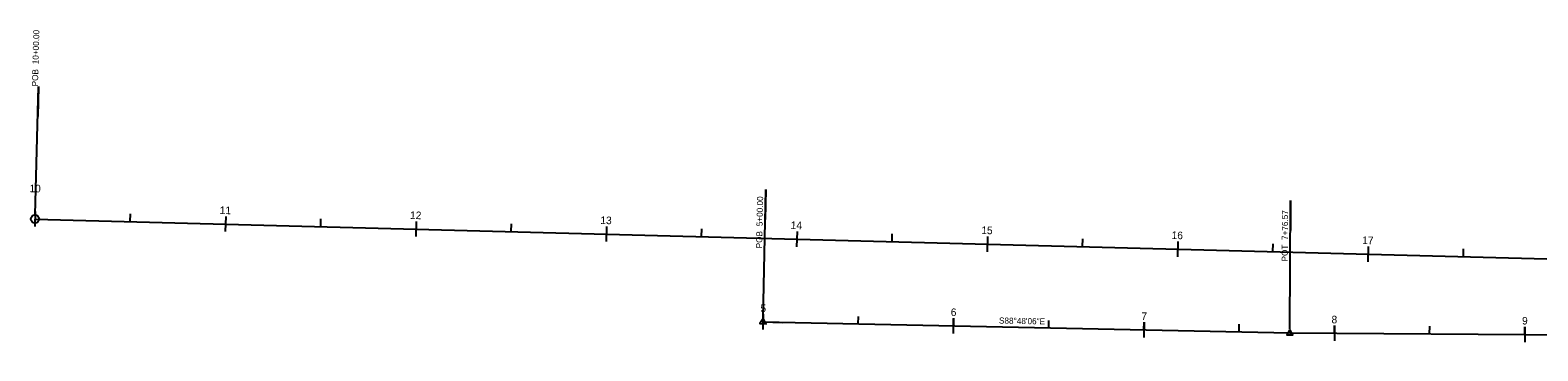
# Model space of a CAD drawing. Extents: x 2343163 to 2348448, y 2217734 to 2218071.
# Drawn here: x 2343163 to 2343954, y 2217867 to 2218036 of the extents above; entities that cross this region are included whole.
import ezdxf

# ---------------------------------------------------------------- set-up
doc = ezdxf.new("R2010")
doc.units = 0
for name, color, linetype in [('ALG_CL_BLUE_Horiz', 7, 'Continuous'), ('ALG_CL_BLUE_Horiz-PC-PT-PI', 7, 'Continuous'), ('ALG_CL_BLUE_Horiz-Stationing', 7, 'Continuous'), ('ALG_CL_MISC_Horiz', 7, 'Continuous'), ('ALG_CL_MISC_Horiz-PC-PT-PI', 7, 'Continuous'), ('ALG_CL_MISC_Horiz-POB-POE', 7, 'Continuous'), ('ALG_CL_MISC_Horiz-Stationing', 7, 'Continuous'), ('ALG_CL_MISC_Horiz-Stationing-100', 7, 'Continuous'), ('ALG_CL_MISC_Horiz-Stationing-500', 7, 'Continuous'), ('ALG_CL_MISC_Horiz-Text', 7, 'Continuous'), ('GEN_CLIP-Clipping-Elements', 7, 'Continuous')]:
    doc.layers.add(name, color=color, linetype=linetype)

msp = doc.modelspace()

# ---------------------------------------------------------------- linework, layer by layer
at = {"layer": 'ALG_CL_BLUE_Horiz'}
for q in [(2345798.16, 2217867.27), (2345791.1, 2217867.46)]:
    msp.add_line((2343165.62, 2217936.47), q, dxfattribs=at)
at = {"layer": 'ALG_CL_BLUE_Horiz-PC-PT-PI'}
for p, q in [((2343165.67, 2217938.61), (2343167.45, 2218006.05)), ((2343167.45, 2218006.05), (2343167.03, 2217990.31)), ((2343165.62, 2217936.47), (2343165.62, 2217936.47))]:
    msp.add_line(p, q, dxfattribs=at)
msp.add_circle((2343165.62, 2217936.47), 2.14, dxfattribs=at)
at = {"layer": 'ALG_CL_BLUE_Horiz-Stationing'}
for p, q in [((2343165.72, 2217940.48), (2343165.51, 2217932.46)), ((2343215.6, 2217935.16), (2343215.7, 2217939.14)), ((2343265.69, 2217937.85), (2343265.48, 2217929.84)), ((2343315.56, 2217932.53), (2343315.67, 2217936.51)), ((2343365.65, 2217935.22), (2343365.44, 2217927.21)), ((2343415.53, 2217929.9), (2343415.63, 2217933.88)), ((2343465.62, 2217932.59), (2343465.41, 2217924.58)), ((2343515.5, 2217927.27), (2343515.6, 2217931.26)), ((2343565.58, 2217929.97), (2343565.37, 2217921.95)), ((2343615.46, 2217924.65), (2343615.57, 2217928.63)), ((2343665.55, 2217927.34), (2343665.34, 2217919.32)), ((2343715.43, 2217922.02), (2343715.53, 2217926)), ((2343765.51, 2217924.71), (2343765.3, 2217916.7)), ((2343815.39, 2217919.39), (2343815.5, 2217923.37)), ((2343865.48, 2217922.08), (2343865.27, 2217914.07)), ((2343915.36, 2217916.76), (2343915.46, 2217920.74))]:
    msp.add_line(p, q, dxfattribs=at)
at = {"layer": 'ALG_CL_MISC_Horiz'}
for p, q in [((2343547.73, 2217882.44), (2343824.25, 2217876.65)), ((2343824.25, 2217876.65), (2344124.31, 2217874.76))]:
    msp.add_line(p, q, dxfattribs=at)
at = {"layer": 'ALG_CL_MISC_Horiz-PC-PT-PI'}
for p, q in [((2343824.26, 2217878.79), (2343824.69, 2217946.25)), ((2343824.69, 2217946.25), (2343824.59, 2217930.51)), ((2343547.73, 2217882.44), (2343547.73, 2217882.44)), ((2343824.25, 2217876.65), (2343824.25, 2217876.65))]:
    msp.add_line(p, q, dxfattribs=at)
for points in [[(2343547.77, 2217884.3), (2343546.11, 2217881.54), (2343549.32, 2217881.48)], [(2343824.26, 2217878.51), (2343822.63, 2217875.74), (2343825.85, 2217875.72)]]:
    msp.add_lwpolyline(points, close=True, dxfattribs=at)
at = {"layer": 'ALG_CL_MISC_Horiz-POB-POE'}
for p, q in [((2343547.78, 2217884.57), (2343549.19, 2217952.02)), ((2343549.19, 2217952.02), (2343548.86, 2217936.28))]:
    msp.add_line(p, q, dxfattribs=at)
at = {"layer": 'ALG_CL_MISC_Horiz-Stationing'}
for p, q in [((2343547.82, 2217886.45), (2343547.65, 2217878.43)), ((2343597.72, 2217881.39), (2343597.81, 2217885.38)), ((2343647.8, 2217884.35), (2343647.63, 2217876.34)), ((2343697.7, 2217879.3), (2343697.78, 2217883.28)), ((2343747.77, 2217882.26), (2343747.61, 2217874.25)), ((2343797.68, 2217877.21), (2343797.76, 2217881.19)), ((2343847.7, 2217880.51), (2343847.65, 2217872.5)), ((2343897.67, 2217876.19), (2343897.7, 2217880.17)), ((2343947.7, 2217879.88), (2343947.65, 2217871.87))]:
    msp.add_line(p, q, dxfattribs=at)
at = {"layer": 'ALG_CL_MISC_Horiz-Stationing-100'}
for p, q in [((2343547.82, 2217886.45), (2343547.65, 2217878.43)), ((2343647.71, 2217880.35), (2343647.8, 2217884.33)), ((2343747.69, 2217878.26), (2343747.77, 2217882.24)), ((2343847.67, 2217876.51), (2343847.7, 2217880.49)), ((2343947.67, 2217875.87), (2343947.7, 2217879.86))]:
    msp.add_line(p, q, dxfattribs=at)
at = {"layer": 'ALG_CL_MISC_Horiz-Stationing-500'}
msp.add_line((2343547.73, 2217882.44), (2343547.82, 2217886.42), dxfattribs=at)
at = {"layer": 'GEN_CLIP-Clipping-Elements'}
msp.add_line((2343547.73, 2217882.44), (2343557.73, 2217882.23), dxfattribs=at)

# ---------------------------------------------------------------- texts
at = {"layer": 'ALG_CL_BLUE_Horiz-PC-PT-PI'}
for s, p in [('10+00.00', (2343167.44, 2218017.66)), ('POB', (2343167.13, 2218006.05))]:
    msp.add_text(s, height=3.216, rotation=88.49424, dxfattribs=at).set_placement(p)
at = {"layer": 'ALG_CL_BLUE_Horiz-Stationing'}
for s, p in [('10', (2343162.64, 2217950.58)), ('11', (2343262.53, 2217939.13)), ('12', (2343362.43, 2217936.51)), ('13', (2343462.34, 2217933.88)), ('14', (2343562.24, 2217931.25)), ('15', (2343662.29, 2217928.62)), ('16', (2343762.19, 2217926)), ('17', (2343862.22, 2217923.37))]:
    msp.add_text(s, height=3.984, rotation=358.49424, dxfattribs=at).set_placement(p)
at = {"layer": 'ALG_CL_MISC_Horiz-PC-PT-PI'}
for s, p in [('7+76.57', (2343823.28, 2217925.44)), ('POT', (2343823.21, 2217914.17))]:
    msp.add_text(s, height=3.216, rotation=89.63771, dxfattribs=at).set_placement(p)
at = {"layer": 'ALG_CL_MISC_Horiz-POB-POE'}
for s, p in [('5+00.00', (2343547.51, 2217932.66)), ('POB', (2343547.27, 2217921.06))]:
    msp.add_text(s, height=3.216, rotation=88.8016, dxfattribs=at).set_placement(p)
at = {"layer": 'ALG_CL_MISC_Horiz-Stationing'}
for s, rotation, p in [('5', 358.8016, (2343546.35, 2217887.68)), ('6', 358.8016, (2343646.26, 2217885.59)), ('7', 358.8016, (2343746.3, 2217883.49)), ('8', 359.63771, (2343846.16, 2217881.72)), ('9', 359.63771, (2343946.17, 2217881.09))]:
    msp.add_text(s, height=3.98, rotation=rotation, dxfattribs=at).set_placement(p)
at = {"layer": 'ALG_CL_MISC_Horiz-Stationing-100'}
msp.add_text('5', height=3.98, rotation=358.8016, dxfattribs=at).set_placement((2343546.35, 2217887.68))
at = {"layer": 'ALG_CL_MISC_Horiz-Text'}
msp.add_text('S88°48\'06"E', height=3.216, rotation=358.8016, dxfattribs=at).set_placement((2343671.57, 2217881.6))

doc.saveas('drawing.dxf')
